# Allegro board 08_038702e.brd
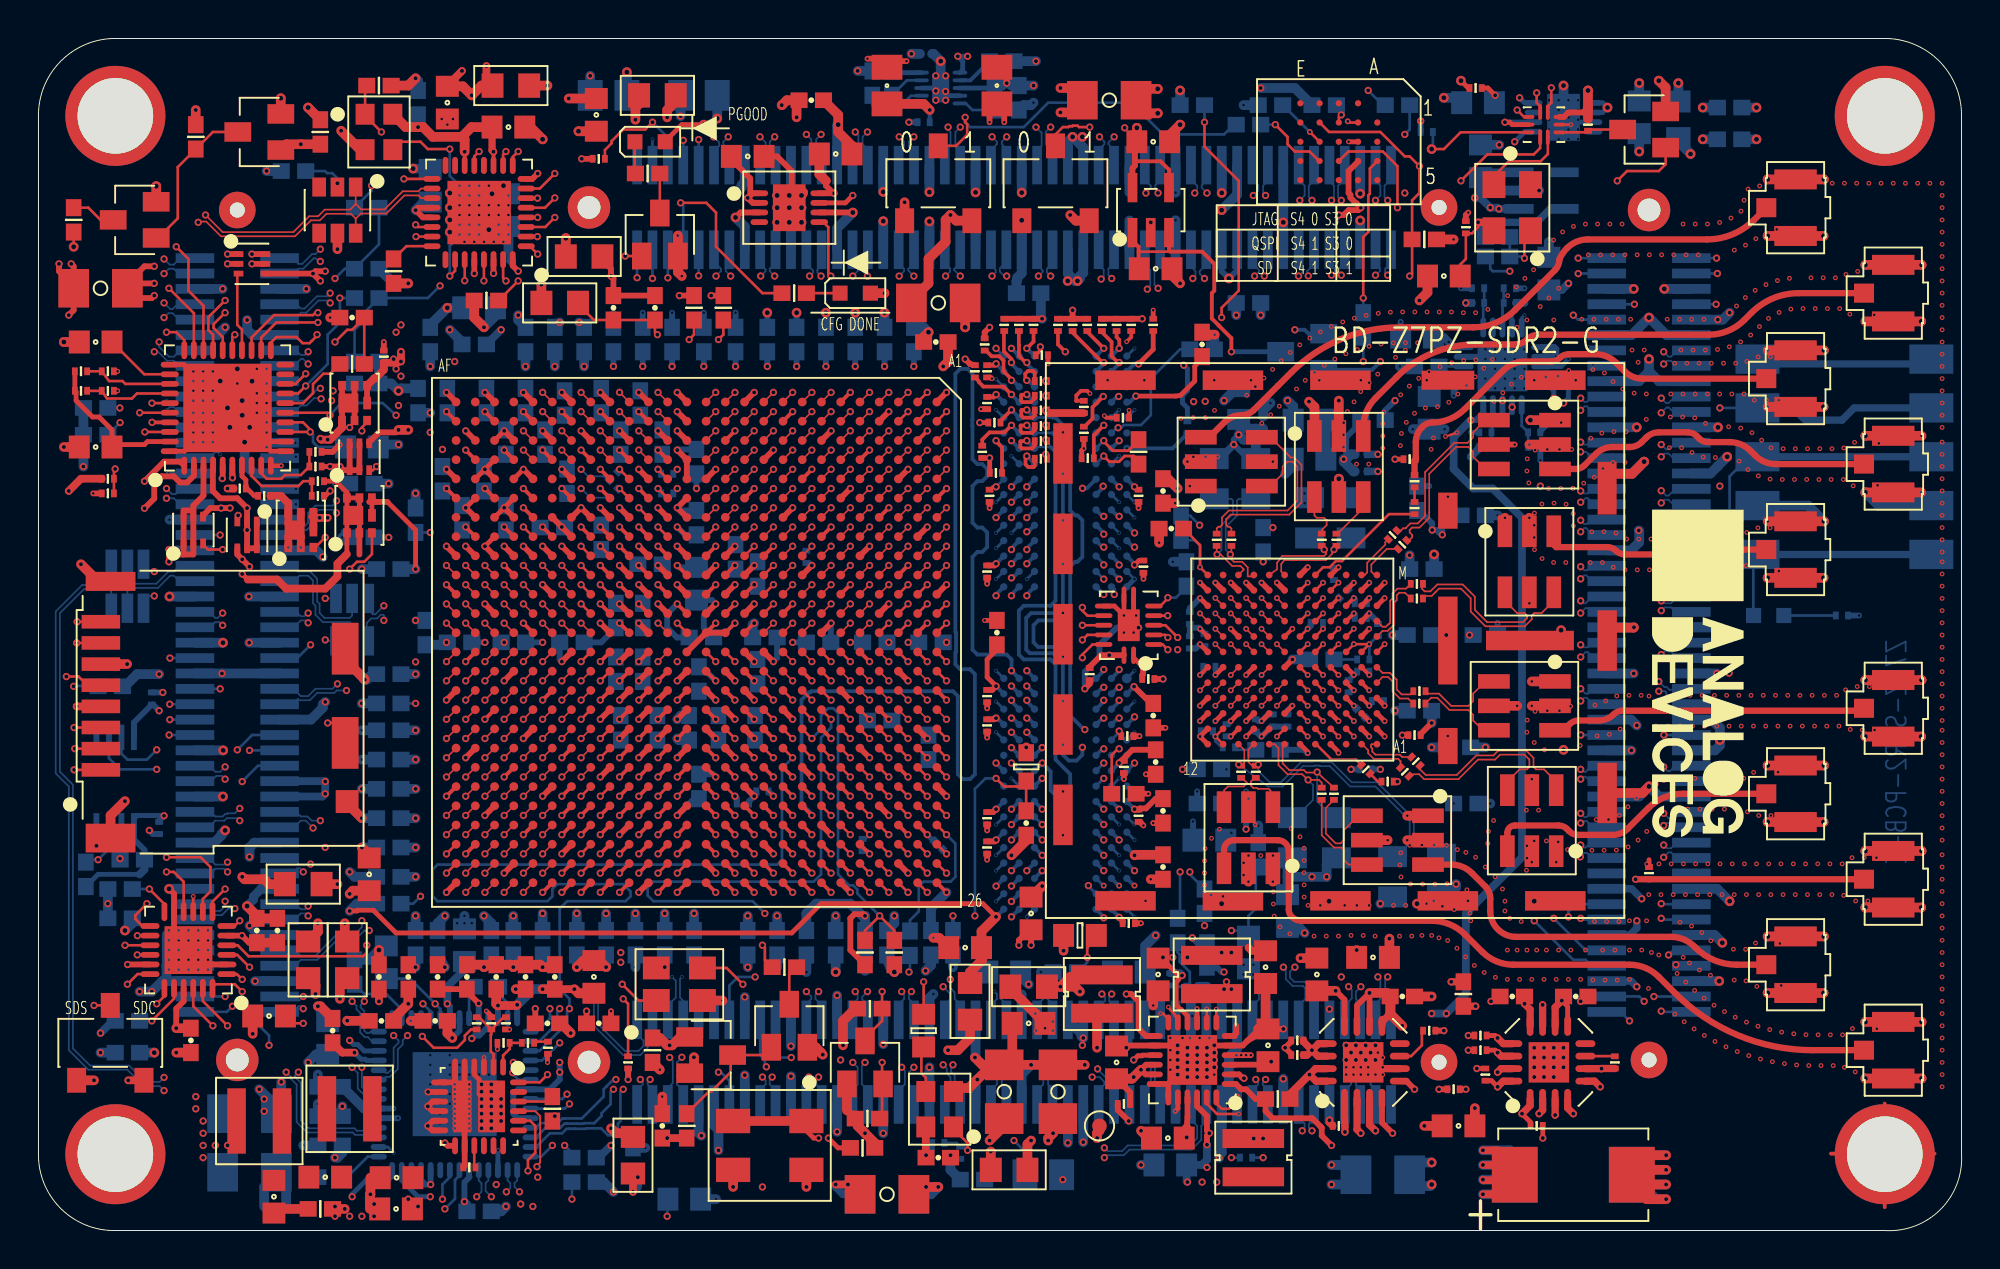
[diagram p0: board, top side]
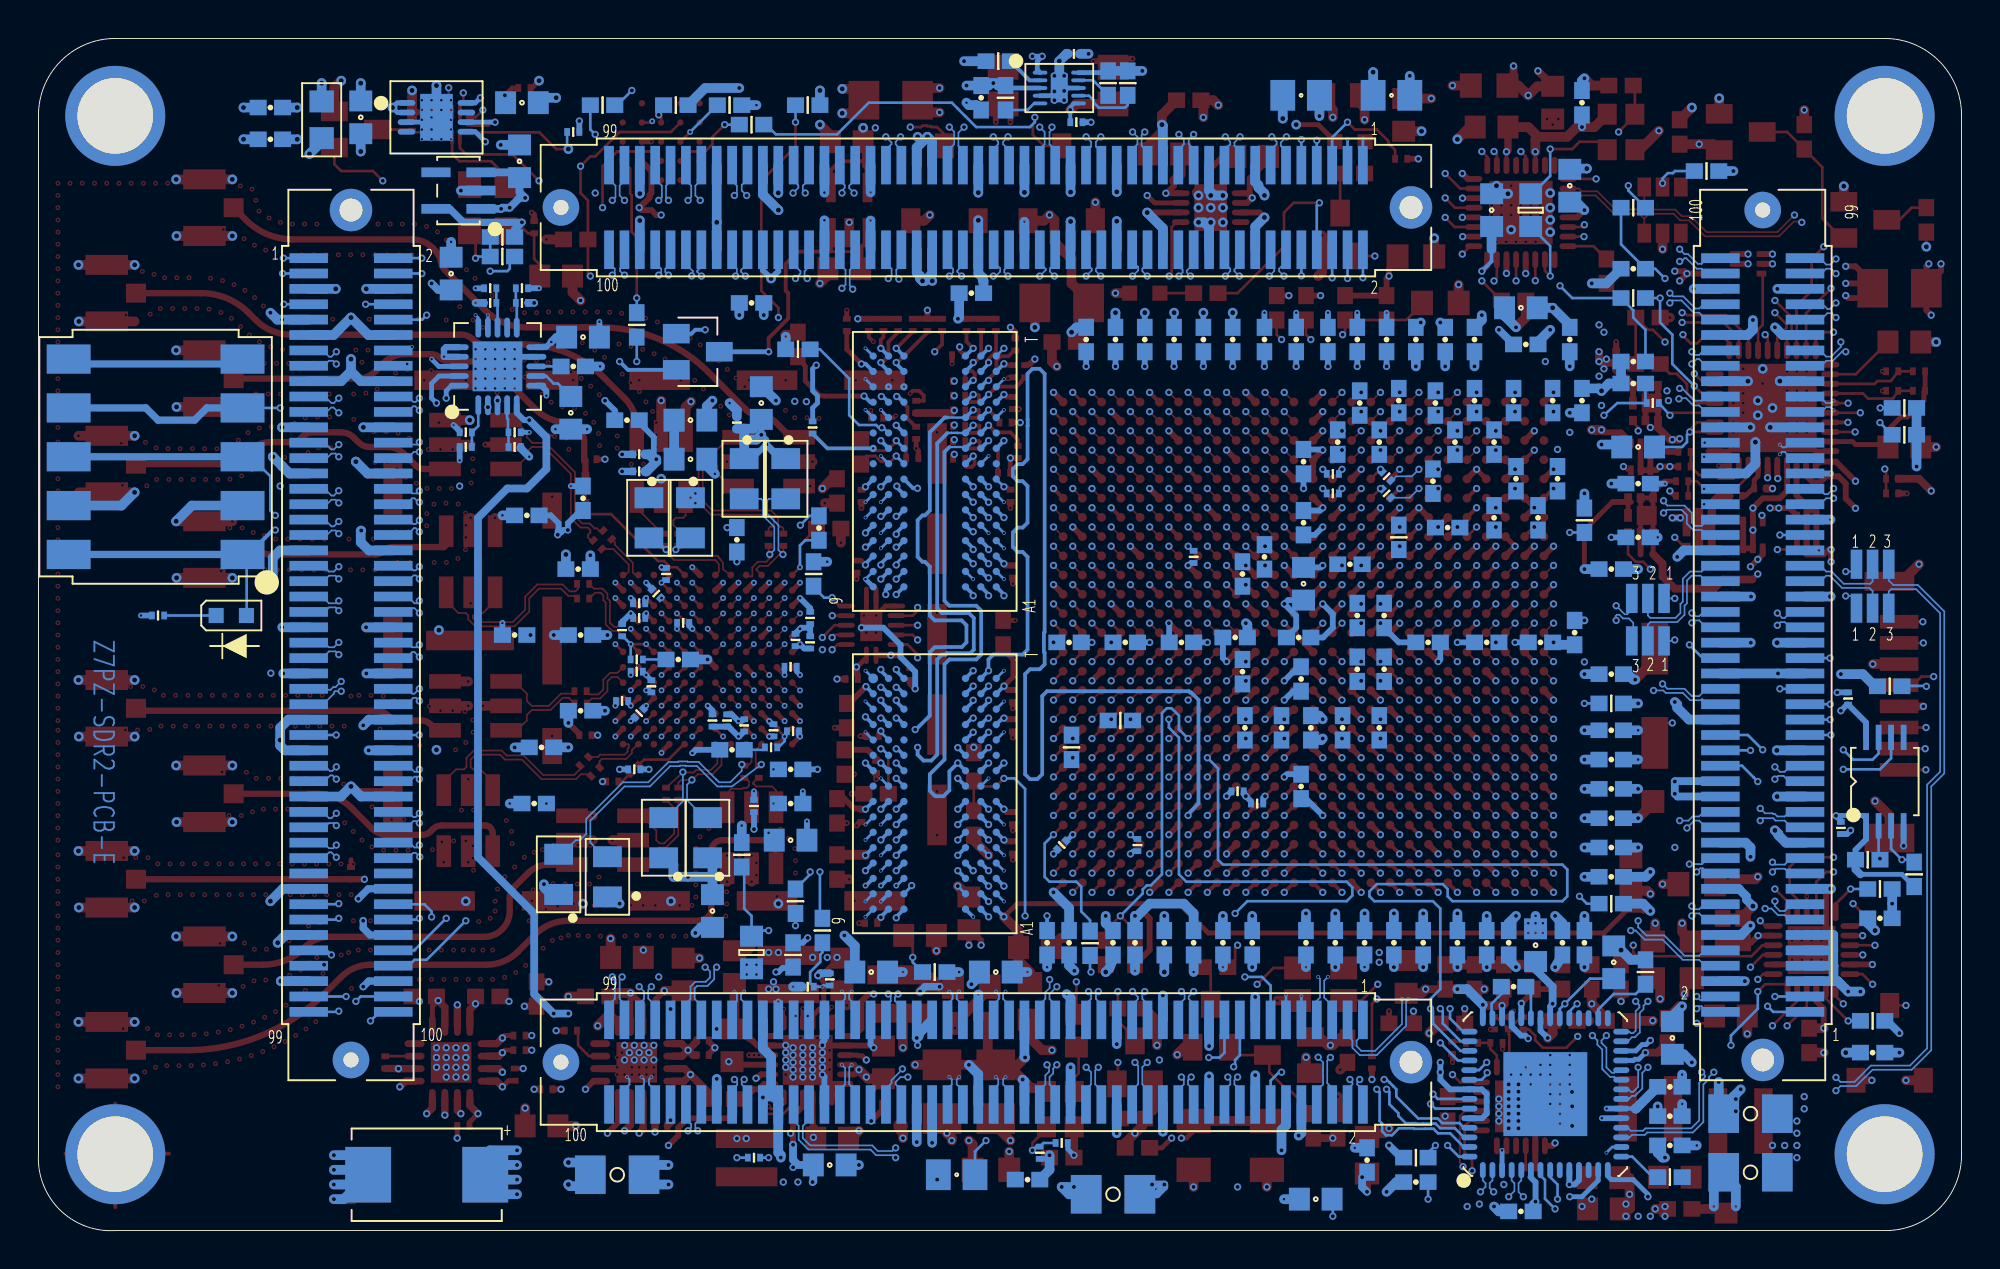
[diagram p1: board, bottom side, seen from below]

Outline 99.99 x 61.99 mm; copper layers: TOP, L2_GND, L3_SIG, L4_SIG, L5_GND, L6_SIG, L7_SIG, L8_GND, L9_POWER, L10_POWER, L11_POWER, L12_POWER, L13_GND, L14_SIG, L15_SIG, L16_GND, L17_SIG, L18_SIG, L19_GND, BOTTOM. Coordinates in mm from the lower left corner of the outline.
Outline path: 0,58 0,4 arc(1.15,1.15) 4,0 96,0 arc(98.9,1.09) 99.99,4 99.99,58 arc(98.83,60.83) 96,61.99 4,61.99 arc(1.17,60.82) 0,58

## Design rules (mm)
constraint set DEFAULT: min track width 0.14
net group DP1: nets UNNAMED_8_CAP_I284_N2 UNNAMED_8_CAP_I285_N2
net group DP2: nets UNNAMED_8_CAP_I220_N2 UNNAMED_8_CAP_I221_N2
net group DP3: nets UNNAMED_8_CAP_I137_N1 UNNAMED_8_CAP_I138_N1
net group DP4: nets UNNAMED_8_CAP_I263_N1 UNNAMED_8_CAP_I264_N1
net group DP5: nets UNNAMED_8_CAP_I209_N2 UNNAMED_8_CAP_I210_N2
net group DP6: nets UNNAMED_8_CAP_I272_N2 UNNAMED_8_CAP_I273_N2
net group DP7: nets UNNAMED_4_CN100PODDEVEN_I17_N4 UNNAMED_4_CN100PODDEVEN_I17_N5
net group DP8: nets UNNAMED_4_CN100PODDEVEN_I16_N4 UNNAMED_4_CN100PODDEVEN_I16_N5
net group DX_0: nets DX_0_N DX_0_P
net group ETH_MD1: nets ETH_MD1_N ETH_MD1_P
net group ETH_MD2: nets ETH_MD2_N ETH_MD2_P
net group ETH_MD3: nets ETH_MD3_N ETH_MD3_P
net group ETH_MD4: nets ETH_MD4_N ETH_MD4_P
net group IO_L23_12_JX2: nets IO_L23_12_JX2_N IO_L23_12_JX2_P
net group RX1A: nets RX1A_N RX1A_P
net group RX1B: nets RX1B_N RX1B_P
net group RX1C: nets UNNAMED_8_CAP_I135_N1 UNNAMED_8_CAP_I136_N1
net group RX1D: nets UNNAMED_8_CAP_I265_N1 UNNAMED_8_CAP_I266_N1
net group RX2A: nets RX2A_N RX2A_P
net group RX2B: nets RX2B_N RX2B_P
net group S_IN: nets S_IN_N S_IN_P
net group S_OUT: nets S_OUT_N S_OUT_P
net group TX1A: nets TX1A_N TX1A_P
net group TX1B: nets TX1B_N TX1B_P
net group TX2A: nets TX2A_N TX2A_P
net group TX2B: nets TX2B_N TX2B_P
net group USB_OTG: nets USB_OTG_N USB_OTG_P
net group AD9361_RX: nets IO_L01_35_RX_D0_P IO_L02_35_RX_D1_P IO_L03_35_RX_D2_P IO_L04_35_RX_D3_P IO_L05_35_RX_D4_P IO_L06_35_RX_D5_P IO_L07_35_RX_FRAME_P IO_L12_MRCC_35_DATA_CLK_P
net group AD9361_TX: nets IO_L08_35_FB_CLK_P IO_L09_35_TX_FRAME_P IO_L13_35_TX_D0_P IO_L14_35_TX_D1_P IO_L15_35_TX_D2_P IO_L16_35_TX_D3_P IO_L17_35_TX_D4_P IO_L18_35_TX_D5_P
net group CARRIER_RESET: nets CARRIER_RESET SDIO_CMDB1 VCC-3P3V-IO
net group DDR3_CK: nets DDR3_CK_N
net group DDR3_CLK2DQS: nets DDR3_DQS0_P DDR3_DQS1_P DDR3_DQS2_P DDR3_DQS3_P
net group DDR3_DQS0: nets DDR3_DQS0_N
net group DDR3_DQS1: nets DDR3_DQS1_N
net group DDR3_DQS2: nets DDR3_DQS2_N
net group DDR3_DQS3: nets DDR3_DQS3_N
net group DDR3_LANE0: nets DDR3_DM0 DDR3_DQ0 DDR3_DQ1 DDR3_DQ2 DDR3_DQ3 DDR3_DQ4 DDR3_DQ5 DDR3_DQ6 DDR3_DQ7
net group DDR3_LANE1: nets DDR3_DM1 DDR3_DQ8 DDR3_DQ9 DDR3_DQ10 DDR3_DQ11 DDR3_DQ12 DDR3_DQ13 DDR3_DQ14 DDR3_DQ15
net group DDR3_LANE2: nets DDR3_DM2 DDR3_DQ16 DDR3_DQ17 DDR3_DQ18 DDR3_DQ19 DDR3_DQ20 DDR3_DQ21 DDR3_DQ22 DDR3_DQ23
net group DDR3_LANE3: nets DDR3_DM3 DDR3_DQ24 DDR3_DQ25 DDR3_DQ26 DDR3_DQ27 DDR3_DQ28 DDR3_DQ29 DDR3_DQ30 DDR3_DQ31
net group IO_L01_12_JX3: nets IO_L01_12_JX3_N
net group IO_L01_13_JX2: nets IO_L01_13_JX2_N
net group IO_L01_33_RX_D0: nets IO_L01_35_RX_D0_N
net group IO_L01_34_JX4: nets IO_L01_34_JX4_N
net group IO_L01_35_JX1: nets IO_L01_33_JX1_N
net group IO_L02_12_JX3: nets IO_L02_12_JX3_N
net group IO_L02_13_JX2: nets IO_L02_13_JX2_N
net group IO_L02_33_RX_D1: nets IO_L02_35_RX_D1_N
net group IO_L02_34_JX4: nets IO_L02_34_JX4_N
net group IO_L02_35_JX1: nets IO_L02_33_JX1_N
net group IO_L03_12_JX3: nets IO_L03_12_JX3_N
net group IO_L03_13_JX2: nets IO_L03_13_JX2_N
net group IO_L03_33_RX_D2: nets IO_L03_35_RX_D2_N
net group IO_L03_34_JX4: nets IO_L03_34_JX4_N
net group IO_L03_35_JX1: nets IO_L03_33_JX1_N
net group IO_L04_12_JX3: nets IO_L04_12_JX3_N
net group IO_L04_13_JX2: nets IO_L04_13_JX2_N
net group IO_L04_33_RX_D3: nets IO_L04_35_RX_D3_N
net group IO_L04_34_JX4: nets IO_L04_34_JX4_N
net group IO_L04_35_JX1: nets IO_L04_33_JX1_N
net group IO_L05_12_JX3: nets IO_L05_12_JX3_N
net group IO_L05_33_JX1: nets IO_L05_33_JX1_N
net group IO_L05_33_RX_D4: nets IO_L05_35_RX_D4_N
net group IO_L05_34_JX4: nets IO_L05_34_JX4_N
net group IO_L06_12_JX3: nets IO_L06_12_JX3_N
net group IO_L06_13_JX2: nets IO_L06_13_JX2_N
net group IO_L06_33_JX1: nets IO_L06_33_JX1_N
net group IO_L06_33_RX_D5: nets IO_L06_35_RX_D5_N
net group IO_L06_34_JX4: nets IO_L06_34_JX4_N
net group IO_L07_12_JX3: nets IO_L07_12_JX3_N
net group IO_L07_13_JX2: nets IO_L07_13_JX2_N
net group IO_L07_33_RX_FRAME: nets IO_L07_35_RX_FRAME_N
net group IO_L07_34_JX4: nets IO_L07_34_JX4_N
net group IO_L07_35_JX1: nets IO_L07_33_JX1_N
net group IO_L08_12_JX3: nets IO_L08_12_JX3_N
net group IO_L08_13_JX2: nets IO_L08_13_JX2_N
net group IO_L08_33_FB_CLK: nets IO_L08_35_FB_CLK_N
net group IO_L08_34_JX4: nets IO_L08_34_JX4_N
net group IO_L08_35_JX1: nets IO_L08_33_JX1_N
net group IO_L09_12_JX3: nets IO_L09_12_JX3_N
net group IO_L09_13_JX2: nets IO_L09_13_JX2_N
net group IO_L09_33_TX_FRAME: nets IO_L09_35_TX_FRAME_N
net group IO_L09_34_JX4: nets IO_L09_34_JX4_N
net group IO_L09_35_JX1: nets IO_L09_33_JX1_N
net group IO_L10_12_JX3: nets IO_L10_12_JX3_N
net group IO_L10_13_JX2: nets IO_L10_13_JX2_N
net group IO_L10_34_JX4: nets IO_L10_34_JX4_N
net group IO_L10_35_JX1: nets IO_L10_33_JX1_N
net group IO_L11_SRCC_12_JX3: nets IO_L11_SRCC_12_JX3_N
net group IO_L11_SRCC_13_JX2: nets IO_L11_SRCC_13_JX2_N
net group IO_L11_SRCC_33_JX1: nets IO_L11_SRCC_33_JX1_N
net group IO_L11_SRCC_34_JX4: nets IO_L11_SRCC_34_JX4_N
net group IO_L12_MRCC_12_JX3: nets IO_L12_MRCC_12_JX3_N
net group IO_L12_MRCC_13_JX2: nets IO_L12_MRCC_13_JX2_N
net group IO_L12_MRCC_33_DATA_CLK: nets IO_L12_MRCC_35_DATA_CLK_N
net group IO_L12_MRCC_34_JX4: nets IO_L12_MRCC_34_JX4_N
net group IO_L12_MRCC_35_JX1: nets IO_L12_MRCC_33_JX1_N
net group IO_L13_33_TX_D0: nets IO_L13_35_TX_D0_N
net group IO_L13_MRCC_12_JX3: nets IO_L13_MRCC_12_JX3_N
net group IO_L13_MRCC_13_JX2: nets IO_L13_MRCC_13_JX2_N
net group IO_L13_MRCC_34_JX4: nets IO_L13_MRCC_34_JX4_N
net group IO_L13_MRCC_35_JX1: nets IO_L13_MRCC_33_JX1_N
net group IO_L14_33_TX_D1: nets IO_L14_35_TX_D1_N
net group IO_L14_SRCC_12_JX3: nets IO_L14_SRCC_12_JX3_N
net group IO_L14_SRCC_13_JX2: nets IO_L14_SRCC_13_JX2_N
net group IO_L14_SRCC_33_JX1: nets IO_L14_SRCC_33_JX1_N
net group IO_L14_SRCC_34_JX4: nets IO_L14_SRCC_34_JX4_N
net group IO_L15_12_JX3: nets IO_L15_12_JX3_N
net group IO_L15_13_JX2: nets IO_L15_13_JX2_N
net group IO_L15_33_JX1: nets IO_L15_33_JX1_N
net group IO_L15_33_TX_D2: nets IO_L15_35_TX_D2_N
net group IO_L15_34_JX4: nets IO_L15_34_JX4_N
net group IO_L16_12_JX3: nets IO_L16_12_JX3_N
net group IO_L16_13_JX2: nets IO_L16_13_JX2_N
net group IO_L16_33_TX_D3: nets IO_L16_35_TX_D3_N
net group IO_L16_34_JX4: nets IO_L16_34_JX4_N
net group IO_L16_35_JX1: nets IO_L16_33_JX1_N
net group IO_L17_12_JX2: nets IO_L17_12_JX2_N
net group IO_L17_13_JX2: nets IO_L17_13_JX2_N
net group IO_L17_33_TX_D4: nets IO_L17_35_TX_D4_N
net group IO_L17_34_JX4: nets IO_L17_34_JX4_N
net group IO_L17_35_JX1: nets IO_L17_33_JX1_N
net group IO_L18_12_JX2: nets IO_L18_12_JX2_N
net group IO_L18_13_JX2: nets IO_L18_13_JX2_N
net group IO_L18_33_TX_D5: nets IO_L18_35_TX_D5_N
net group IO_L18_34_JX4: nets IO_L18_34_JX4_N
net group IO_L18_35_JX1: nets IO_L18_33_JX1_N
net group IO_L19_12_JX2: nets IO_L19_12_JX2_N
net group IO_L19_13_JX2: nets IO_L19_13_JX2_N
net group IO_L19_33_JX1: nets IO_L19_33_JX1_N
net group IO_L19_34_JX4: nets IO_L19_34_JX4_N
net group IO_L20_12_JX2: nets IO_L20_12_JX2_N
net group IO_L20_13_JX2: nets IO_L20_13_JX2_N
net group IO_L20_33_JX1: nets IO_L20_33_JX1_N
net group IO_L20_34_JX4: nets IO_L20_34_JX4_N
net group IO_L21_12_JX2: nets IO_L21_12_JX2_N
net group IO_L21_13_JX2: nets IO_L21_13_JX2_N
net group IO_L21_33_JX1: nets IO_L21_33_JX1_N
net group IO_L21_34_JX4: nets IO_L21_34_JX4_N
net group IO_L22_12_JX2: nets IO_L22_12_JX2_N
net group IO_L22_13_JX2: nets IO_L22_13_JX2_N
net group IO_L22_33_JX1: nets IO_L22_33_JX1_N
net group IO_L22_34_JX4: nets IO_L22_34_JX4_N
net group IO_L23_13_JX2: nets IO_L23_13_JX2_N
net group IO_L23_33_JX1: nets IO_L23_33_JX1_N
net group IO_L24_12_JX4: nets IO_L24_12_JX4_N
net group IO_L24_13_JX2: nets IO_L24_13_JX2_N
net group IO_L24_33_JX1: nets IO_L24_33_JX1_N
net group JX_PAIRS: nets IO_00_33_JX1 IO_25_13_JX2 IO_25_33_JX1 IO_L01_12_JX3_P IO_L01_13_JX2_P IO_L01_33_JX1_P IO_L01_34_JX4_P IO_L02_12_JX3_P IO_L02_13_JX2_P IO_L02_33_JX1_P IO_L02_34_JX4_P IO_L03_12_JX3_P IO_L03_13_JX2_P IO_L03_33_JX1_P IO_L03_34_JX4_P IO_L04_12_JX3_P IO_L04_13_JX2_P IO_L04_33_JX1_P IO_L04_34_JX4_P IO_L05_12_JX3_P IO_L05_33_JX1_P IO_L05_34_JX4_P IO_L06_12_JX3_P IO_L06_13_JX2_P IO_L06_33_JX1_P IO_L06_34_JX4_P IO_L07_12_JX3_P IO_L07_13_JX2_P IO_L07_33_JX1_P IO_L07_34_JX4_P IO_L08_12_JX3_P IO_L08_13_JX2_P IO_L08_33_JX1_P IO_L08_34_JX4_P IO_L09_12_JX3_P IO_L09_13_JX2_P IO_L09_33_JX1_P IO_L09_34_JX4_P IO_L10_12_JX3_P IO_L10_13_JX2_P IO_L10_33_JX1_P IO_L10_34_JX4_P IO_L11_SRCC_12_JX3_P IO_L11_SRCC_13_JX2_P IO_L11_SRCC_33_JX1_P IO_L11_SRCC_34_JX4_P IO_L12_MRCC_12_JX3_P IO_L12_MRCC_13_JX2_P IO_L12_MRCC_33_JX1_P IO_L12_MRCC_34_JX4_P IO_L13_MRCC_12_JX3_P IO_L13_MRCC_13_JX2_P IO_L13_MRCC_33_JX1_P IO_L13_MRCC_34_JX4_P IO_L14_SRCC_12_JX3_P IO_L14_SRCC_13_JX2_P IO_L14_SRCC_33_JX1_P IO_L14_SRCC_34_JX4_P IO_L15_12_JX3_P IO_L15_13_JX2_P IO_L15_33_JX1_P IO_L15_34_JX4_P IO_L16_12_JX3_P IO_L16_13_JX2_P IO_L16_33_JX1_P IO_L16_34_JX4_P IO_L17_12_JX2_P IO_L17_13_JX2_P IO_L17_33_JX1_P IO_L17_34_JX4_P IO_L18_12_JX2_P IO_L18_13_JX2_P IO_L18_33_JX1_P IO_L18_34_JX4_P IO_L19_12_JX2_P IO_L19_13_JX2_P IO_L19_33_JX1_P IO_L19_34_JX4_P IO_L20_12_JX2_P IO_L20_13_JX2_P IO_L20_33_JX1_P IO_L20_34_JX4_P IO_L21_12_JX2_P IO_L21_13_JX2_P IO_L21_33_JX1_P IO_L21_34_JX4_P IO_L22_12_JX2_P IO_L22_13_JX2_P IO_L22_33_JX1_P IO_L22_34_JX4_P IO_L23_13_JX2_P IO_L23_33_JX1_P IO_L24_12_JX4_P IO_L24_13_JX2_P IO_L24_33_JX1_P
net group MGTREFCLK0_112_JX1: nets MGTREFCLK0_112_JX1_N
net group MGTREFCLK1_112_JX3: nets MGTREFCLK1_112_JX3_N
net group MGTX: nets MGTREFCLK0_112_JX1_P MGTREFCLK1_112_JX3_P MGTXRX0_112_JX1_P MGTXRX1_112_JX1_P MGTXRX2_112_JX1_P MGTXRX3_112_JX1_P MGTXTX0_112_JX3_P MGTXTX1_112_JX3_P MGTXTX2_112_JX3_P MGTXTX3_112_JX3_P
net group MGTXRX0_112_JX1: nets MGTXRX0_112_JX1_N
net group MGTXRX1_112_JX1: nets MGTXRX1_112_JX1_N
net group MGTXRX2_112_JX1: nets MGTXRX2_112_JX1_N
net group MGTXRX3_112_JX1: nets MGTXRX3_112_JX1_N
net group MGTXTX0_112_JX3: nets MGTXTX0_112_JX3_N
net group MGTXTX1_112_JX3: nets MGTXTX1_112_JX3_N
net group MGTXTX2_112_JX3: nets MGTXTX2_112_JX3_N
net group MGTXTX3_112_JX3: nets MGTXTX3_112_JX3_N
net group PS_MIO_A: nets PS_MIO07_500_USB_RESET_B PS_MIO09_500_USB_CLK_PD PS_MIO28_501_USB0_D4 PS_MIO29_501_USB0_DIR PS_MIO30_501_USB0_STP PS_MIO31_501_USB0_NXT PS_MIO32_501_USB0_D0 PS_MIO33_501_USB0_D1 PS_MIO34_501_USB0_D2 PS_MIO35_501_USB0_D3 PS_MIO36_501_USB0_CLK PS_MIO37_501_USB0_D5 PS_MIO38_501_USB0_D6 PS_MIO39_501_USB0_D7
net group PS_MIO_C: nets PS_MIO01_500_QSPI0_SS_B PS_MIO02_500_QSPI0_IO0 PS_MIO03_500_QSPI0_IO1 PS_MIO04_500_QSPI0_IO2 PS_MIO05_500_QSPI0_IO3 PS_MIO06_500_QSPI0_SCLK
net group PS_MIO_E: nets PS_MIO08_500_ETH0_RESETN PS_MIO16_501_ETH0_TX_CLK PS_MIO17_501_ETH0_TX_D0 PS_MIO18_501_ETH0_TX_D1 PS_MIO19_501_ETH0_TX_D2 PS_MIO20_501_ETH0_TX_D3 PS_MIO21_501_ETH0_TX_CTL PS_MIO22_501_ETH0_RX_CLK PS_MIO23_501_ETH0_RX_D0 PS_MIO24_501_ETH0_RX_D1 PS_MIO25_501_ETH0_RX_D2 PS_MIO26_501_ETH0_RX_D3 PS_MIO27_501_ETH0_RX_CTL PS_MIO52_501_ETH0_MDC PS_MIO53_501_ETH0_MDIO

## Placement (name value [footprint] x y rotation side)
C1  0.01uF  [C0201]  69.65 27.54 0 bottom
C2  1uF  [C0402]  75.24 30.97 0 bottom
C3  1uF  [C0402]  69.39 42.15 0 bottom
C4  0.01uF  [C0201]  68.12 28.3 90 bottom
C5  4.7uF  [C0603]  73.08 49.64 180 top
C6  0.001uF  [C0201]  71.55 37.57 270 top
C7  0.001uF  [C0201]  69.01 23.98 135 top
C8  18pF  [C0201]  70.41 36.18 225 top
C9  18pF  [C0201]  70.92 35.67 225 top
C10  18pF  [C0201]  71.62 24.4 135 top
C11  18pF  [C0201]  71.05 23.86 135 top
C12  1uF  [C0402]  66.73 29.7 180 bottom
C13  0.001uF  [C0201]  69.65 31.22 90 bottom
C14  0.001uF  [C0201]  68.76 39.48 180 bottom
C15  4.7uF  [C0402]  37.9 46.34 90 bottom
C16  0.001uF  [C0201]  68.76 40.37 180 bottom
C17  4.7uF  [C0402]  34.6 46.34 90 bottom
C18  0.47uF  [C0402]  31.42 46.34 90 bottom
C19  0.001uF  [C0201]  62.79 22.08 270 bottom
C20  0.001uF  [C0201]  63.68 42.02 270 bottom
C21  10uF  [C0603]  66.09 40.11 180 bottom
C22  10uF  [C0603]  66.09 42.15 180 bottom
C23  10uF  [C0603]  64.95 16.62 270 bottom
C24  10uF  [C0603]  62.41 43.03 90 bottom
C25  18pF  [C0201]  66.73 35.92 90 top
C26  18pF  [C0201]  67.49 35.92 90 top
C27  0.47uF  [C0402]  40.95 46.34 90 bottom
C28  0.1uF  [C0402]  26.85 46.34 90 bottom
C29  18pF  [C0201]  61.27 35.92 90 top
C30  18pF  [C0201]  62.03 35.92 90 top
C31  0.1uF  [C0402]  43.99 46.34 90 bottom
C32  18pF  [C0201]  67.36 22.71 270 top
C33  18pF  [C0201]  66.73 22.71 270 top
C34  18pF  [C0201]  63.3 23.86 270 top
C35  18pF  [C0201]  62.54 23.86 270 top
C36  1uF  [C0603]  41.45 55.99 0 top
C37  0.1uF  [C0402]  46.41 30.59 0 bottom
C38  10uF  [C0603]  36.88 55.86 0 top
C39  0.1uF  [C0402]  46.79 3.79 0 top
C40  0.1uF  [C0402]  62.92 48.24 0 bottom
C41  0.1uF  [C0402]  7.93 9.89 270 top
C42  0.1uF  [C0402]  4.24 16.24 0 bottom
C43  0.01uF  [C0201]  46.15 61.2 180 bottom
C44  680uF  [CPLSML287W169H118]  79.81 2.9 0 top
C45  0.1uF  [C0201]  32.69 39.35 180 bottom
C46  0.1uF  [C0201]  29.9 38.34 45 bottom
C47  0.1uF  [C0201]  32.69 38.34 180 bottom
C48  0.1uF  [C0201]  29.9 39.22 45 bottom
C49  4.7uF  [C0402]  17.71 13.19 90 top
C50  4.7uF  [C0402]  26.47 10.78 0 top
C51  18pF  [C0201]  71.67 33.63 180 top
C52  18pF  [C0201]  71.67 32.87 180 top
C53  18pF  [C0201]  71.81 28.05 180 top
C54  0.1uF  [C0402]  11.36 15.6 90 top
C55  0.1uF  [C0402]  12.42 15.6 90 top
C56  18pF  [C0201]  71.8 27.41 180 top
C57  0.1uF  [C0402]  4.62 9.25 0 bottom
C58  1uF  [C0603]  28.88 13.19 90 top
C59  27PF  [C0603]  11.99 11.16 180 top
C60  27PF  [C0603]  18.09 13.95 90 bottom
C61  10uF  [C0603]  58.73 4.81 180 top
C62  10uF  [C0603]  63.93 9.63 90 top
C63  4.7uF  [C0402]  26.85 13.19 90 top
C64  4.7uF  [C0402]  26.34 41 90 bottom
C65  10uF  [C0603]  56.06 8.74 90 top
C66  0.1uF  [C0201]  56.44 6.59 180 top
C67  22uF  [C0603]  58.22 13.32 270 top
C68  22uF  [C0603]  63.81 13.7 270 top
C69  22uF  [C0603]  58.85 3.41 180 bottom
C70  4.7uF  [C0402]  29.9 46.34 90 bottom
C71  4.7uF  [C0402]  45.52 46.34 90 bottom
C72  0.47uF  [C0402]  42.47 46.34 90 bottom
C73  0.1uF  [C0402]  23.8 13.19 90 top
C74  4.7uF  [C0402]  15.17 4.43 180 bottom
C75  0.1uF  [C0402]  22.91 1 0 bottom
C76  0.01uF  [C0201]  37.64 22.84 180 bottom
C77  0.01uF  [C0201]  36.63 22.21 0 bottom
C78  1uF  [C0603]  17.2 18.52 90 top
C79  10uF  [C0805H60]  49.84 59.54 270 top
C80  0.015uF  [C0402]  50.98 58.91 270 bottom
C81  0.22UF  [C0805]  44.12 59.54 90 top
C82  10uF  [C0805H60]  34.34 59.04 0 bottom
C83  10uF  [C0805H60]  29.64 59.04 0 bottom
C84  0.01uF  [C0201]  46.03 57.64 180 bottom
C85  680uF  [CPLSML287W169H118]  79.81 2.9 0 bottom
C86  4.7uF  [C0402]  58.47 18.9 270 top
C87  4.7uF  [C0402]  58.09 24.37 270 top
C88  0.47uF  [C0402]  57.96 26.78 270 top
C89  0.47uF  [C0402]  58.47 21.83 270 top
C90  0.47uF  [C0402]  32.95 46.34 90 bottom
C91  0.1uF  [C0201]  56.69 15.98 0 top
C92  0.1uF  [C0201]  49.33 19.92 270 top
C93  0.1uF  [C0402]  36.25 46.34 90 bottom
C94  0.1uF  [C0201]  56.44 24.11 270 top
C95  0.1uF  [C0201]  57.2 21.57 270 top
C96  0.1uF  [C0201]  49.33 27.79 270 top
C97  0.1uF  [C0201]  49.33 26.27 270 top
C98  0.1uF  [C0402]  39.42 46.34 90 bottom
C99  4.7uF  [C0402]  25.33 46.34 90 bottom
C100  100uF  [C1206H71]  55.68 58.78 0 top
C101  4.7uF  [C0402]  51.49 48.75 180 bottom
C102  0.01uF  [C0201]  49.46 38.21 270 top
C103  0.01uF  [C0201]  49.33 21.44 270 top
C104  0.001uF  [C0201]  60.76 25.97 0 bottom
C105  1uF  [C0402]  63.93 25 0 bottom
C106  4.7uF  [C0402]  60.5 46.08 90 top
C107  0.47uF  [C0402]  58.47 38.46 270 top
C108  0.47uF  [C0402]  49.84 31.1 90 top
C109  0.1uF  [C0201]  49.33 34.27 270 top
C110  4.7uF  [C0402]  44.12 14.97 270 bottom
C111  4.7uF  [C0402]  18.21 24.49 180 bottom
C112  0.1uF  [C0201]  49.33 43.03 270 top
C113  0.1uF  [C0201]  74.22 52.18 90 top
C114  0.47uF  [C0402]  28.37 46.34 90 bottom
C115  0.1uF  [C0201]  49.33 44.69 270 top
C116  0.1uF  [C0201]  57.96 47.1 90 top
C117  0.1uF  [C0201]  57.2 38.21 270 top
C118  0.1uF  [C0201]  57.46 34.53 270 top
C119  0.1uF  [C0402]  36.25 35.03 90 bottom
C120  4.7uF  [C0402]  40.18 58.78 0 top
C121  4.7uF  [C0402]  31.04 14.97 270 bottom
C122  0.01uF  [C0201]  56.39 42.27 180 top
C123  0.01uF  [C0201]  56.62 25.71 180 top
C124  10uF  [C0603]  71.68 46.46 180 bottom
C125  0.47uF  [C0402]  48.57 2.65 180 bottom
C126  0.1uF  [C0402]  27.99 14.97 270 bottom
C127  0.1uF  [C0402]  36.88 14.97 270 bottom
C128  0.1uF  [C0402]  29.52 14.97 270 bottom
C129  0.1uF  [C0402]  32.56 14.97 270 bottom
C130  0.1uF  [C0402]  34.34 23.1 270 bottom
C131  0.1uF  [C0402]  41.45 14.97 270 bottom
C132  0.1uF  [C0402]  18.21 18.4 180 bottom
C133  4.7uF  [C0402]  72.19 44.94 180 bottom
C134  10uF  [C0603]  78.54 49.77 90 bottom
C135  0.1uF  [C0402]  18.21 22.97 180 bottom
C136  0.1uF  [C0402]  38.41 14.97 270 bottom
C137  0.1uF  [C0402]  34.09 14.97 270 bottom
C138  100uF  [C1206H71]  50.22 7.22 90 top
C139  100uF  [C1206H71]  53.01 7.22 90 top
C140  4.7uF  [C0402]  37.39 29.06 90 bottom
C141  4.7uF  [C0402]  37.39 34.14 90 bottom
C142  4.7uF  [C0402]  30.02 31.99 90 bottom
C143  0.47uF  [C0402]  31.42 29.19 270 bottom
C144  4.7uF  [C0402]  18.21 28.94 180 bottom
C145  0.47uF  [C0402]  46.66 46.21 180 top
C146  0.47uF  [C0402]  18.21 19.92 180 bottom
C147  0.1uF  [C0402]  47.55 14.97 270 bottom
C148  0.1uF  [C0402]  34.34 28.68 270 bottom
C149  0.1uF  [C0402]  34.47 30.84 0 bottom
C150  0.1uF  [C0402]  27.74 30.59 180 bottom
C151  0.1uF  [C0402]  31.42 31.99 270 bottom
C152  0.1uF  [C0402]  37.77 30.84 0 bottom
C153  0.47uF  [C0402]  23.55 14.97 270 bottom
C154  0.1uF  [C0402]  34.22 39.99 90 bottom
C155  0.1uF  [C0402]  30.02 29.19 90 bottom
C156  0.1uF  [C0402]  24.69 30.59 180 bottom
C157  0.1uF  [C0402]  26.21 14.97 270 bottom
C158  10uF  [C0603]  72.32 42.53 270 bottom
C159  4.7uF  [C0402]  33.83 26.14 90 bottom
C160  0.1uF  [C0402]  18.21 21.44 180 bottom
C161  4.7uF  [C0402]  35.36 26.14 270 bottom
C162  0.47uF  [C0402]  30.28 26.14 270 bottom
C163  0.47uF  [C0402]  32.18 26.14 270 bottom
C164  0.1uF  [C0402]  37.26 26.14 270 bottom
C165  18PF  [C0402]  58.9 36.51 180 top
C166  0.1uF  [C0402]  22.66 46.08 180 bottom
C167  4.7uF  [C0402]  18.21 26.02 180 bottom
C168  0.1uF  [C0402]  19.74 58.66 90 bottom
C169  4.7uF  [C0402]  20.75 14.97 270 bottom
C170  0.47uF  [C0402]  20.12 31.1 270 bottom
C171  0.47uF  [C0402]  18.21 34.4 180 bottom
C172  100uF  [C1206H71]  46.79 48.24 0 top
C173  100uF  [C1206H71]  69.9 2.9 0 bottom
C174  4.7uF  [C0402]  39.93 14.97 270 bottom
C175  4.7uF  [C0402]  21.9 30.59 180 bottom
C176  4.7uF  [C0402]  46.41 14.97 270 bottom
C177  4.7uF  [C0402]  42.98 14.97 270 bottom
C178  0.47uF  [C0402]  51.36 21.19 270 top
C179  0.47uF  [C0402]  34.22 36.81 90 bottom
C180  100uF  [C1206H71]  3.23 49 180 top
C181  1uF  [C0603]  24.44 53.07 90 bottom
C182  1uF  [C0603]  22.91 47.99 180 bottom
C183  1uF  [C0603]  24.44 57.39 0 top
C184  1uF  [C0603]  20.37 54.34 90 bottom
C185  0.1uF  [C0402]  19.61 14.97 270 bottom
C186  0.1uF  [C0402]  24.69 14.97 270 bottom
C187  0.1uF  [C0402]  31.8 34.65 0 bottom
C188  0.1uF  [C0201]  74.73 59.42 180 top
C189  0.47uF  [C0402]  29.9 47.99 90 top
C190  0.1uF  [C0402]  32.06 47.99 90 top
C191  10uF  [C0603]  51.49 10.78 180 top
C192  10uF  [C0603]  48.19 14.71 180 top
C193  10uF  [C0603]  51.61 16.49 90 top
C194  10uF  [C0603]  50.22 13.44 180 bottom
C195  10uF  [C0603]  56.69 13.44 180 bottom
C196  10uF  [C0603]  21.26 58.66 270 top
C197  10uF  [C0603]  29.01 58.02 270 top
C198  10uF  [C0603]  34.22 33.64 270 bottom
C199  1uF  [C0603]  74.86 58.66 180 bottom
C200  10uF  [C0603]  83.24 57.89 270 bottom
C201  0.1uF  [C0402]  20.75 13.19 90 top
C202  10uF  [C0603]  16.82 40.75 0 bottom
C203  0.1uF  [C0402]  17.83 10.9 180 top
C204  10uF  [C0603]  2.97 46.21 180 top
C205  10uF  [C0603]  2.97 40.75 180 top
C206  0.1uF  [C0402]  15.17 5.95 180 bottom
C207  220pF  [C0402]  17.07 44.05 0 bottom
C208  0.1uF  [C0402]  15.29 10.4 90 top
C209  220pF  [C0402]  16.31 47.48 180 top
C210  10uF  [C0603]  22.15 14.84 90 bottom
C211  0.1uF  [C0402]  19.23 13.19 90 top
C212  0.1uF  [C0402]  30.91 3.66 90 bottom
C213  220pF  [C0402]  17.07 45.19 0 bottom
C214  0.1uF  [C0402]  15.17 7.47 180 bottom
C215  220pF  [C0402]  17.07 50.02 0 bottom
C216  18PF  [C0402]  59.41 36.53 270 bottom
C217  0.1uF  [C0402]  25.33 13.19 90 top
C218  4.7uF  [C0402]  22.28 13.19 90 top
C219  1uF  [C0603]  15.04 10.01 90 bottom
C220  4.7uF  [C0402]  16.82 38.84 180 bottom
C221  4.7uF  [C0402]  19.74 43.16 90 bottom
C222  0.47uF  [C0402]  16.82 36.05 180 bottom
C223  4.7uF  [C0402]  20.37 46.34 90 bottom
C224  0.1uF  [C0402]  32.44 5.44 90 top
C225  0.1uF  [C0402]  29.14 10.78 0 top
C226  0.1uF  [C0402]  20.63 10.9 180 top
C227  0.1uF  [C0402]  30.28 41 90 bottom
C228  0.47uF  [C0402]  31.29 43.03 90 bottom
C229  0.1uF  [C0402]  23.17 39.1 90 bottom
C230  0.1uF  [C0402]  25.33 43.16 90 bottom
C231  0.1uF  [C0402]  26.72 36.56 0 bottom
C232  0.1uF  [C0402]  21.01 39.1 90 bottom
C233  0.1uF  [C0402]  32.44 41 90 bottom
C234  0.1uF  [C0402]  24.31 41 90 bottom
C235  0.1uF  [C0402]  24.31 37.07 90 bottom
C236  0.1uF  [C0402]  29.26 43.16 90 bottom
C237  0.1uF  [C0402]  22.02 37.07 90 bottom
C238  0.1uF  [C0402]  21.26 43.16 90 bottom
C239  0.1uF  [C0402]  27.48 38.97 90 bottom
C240  0.1uF  [C0402]  23.29 43.16 90 bottom
C241  0.1uF  [C0402]  27.36 43.03 90 bottom
C242  0.1uF  [C0402]  23.29 12.68 180 bottom
C243  0.1uF  [C0201]  6.28 20.94 90 bottom
C244  0.1uF  [C0201]  5.89 27.67 270 bottom
C245  0.1uF  [C0201]  57.71 28.68 0 top
C246  0.1uF  [C0201]  54.66 28.94 270 top
C247  2.2uF  [C0603]  58.09 50.02 0 top
C248  2.2uF  [C0603]  57.96 56.62 0 top
C249  0.1uF  [C0402]  40.57 30.59 0 bottom
C250  0.1uF  [C0402]  43.49 30.59 0 bottom
C251  47uF  [C0805H60]  52.25 2.9 0 bottom
C252  0.039uF  [C0603]  33.58 1.63 0 bottom
C253  0.1uF  [C0201]  22.4 3.28 0 top
C254  1uF  [C0402]  28.37 2.52 0 bottom
C255  0.0022uF  [C0201]  25.45 9.76 0 top
C256  39PF  [C0201]  24.18 9.76 180 top
C257  2.2UF  [C0603]  12.24 1.76 270 top
C258  100uF  [C1206H71]  44.12 1.89 0 top
C259  100uF  [C1206H71]  44.12 1.89 0 bottom
C260  4.7uF  [C0603]  74.98 55.61 90 bottom
C301  10uF  [C0603]  18.59 1.12 180 top
C305  2.2uF  [C0603]  14.91 2.78 0 top
C308  100uF  [C1206H71]  10.97 6.08 0 bottom
C309  100uF  [C1206H71]  10.97 3.03 0 bottom
C310  0.1uF  [C0201]  77.9 5.44 0 top
C311  0.01uF  [C0201]  72.32 10.4 0 top
C312  10uF  [C0603]  69.39 14.21 0 top
C313  10uF  [C0603]  66.47 13.32 90 top
C314  0.1uF  [C0201]  65.46 9.89 180 top
C315  0.1uF  [C0201]  65.46 9.13 180 top
C318  0.1uF  [C0201]  67.62 5.44 180 top
C319  0.1uF  [C0201]  64.19 26.52 90 bottom
C320  1uF  [C0402]  70.92 12.17 0 top
C321  0.01uF  [C0201]  61.77 26.02 90 bottom
C322  0.01uF  [C0201]  68.89 29.06 180 bottom
C323  1uF  [C0402]  71.81 27.03 0 bottom
C324  1uF  [C0402]  71.68 38.08 90 bottom
C325  0.01uF  [C0201]  68.76 26.91 315 bottom
C326  0.01uF  [C0201]  68.76 32.62 0 bottom
C327  1uF  [C0402]  71.93 34.4 0 bottom
C328  1uF  [C0402]  71.81 30.97 0 bottom
C329  0.01uF  [C0201]  68.76 31.86 0 bottom
C330  0.01uF  [C0201]  60.89 29.32 0 bottom
C331  1uF  [C0402]  74.6 37.19 0 bottom
C332  1uF  [C0402]  74.22 22.21 0 bottom
C333  0.01uF  [C0201]  67.87 33.13 45 bottom
C334  0.01uF  [C0201]  69.01 23.98 0 bottom
C335  1uF  [C0402]  63.68 35.92 90 bottom
C336  1uF  [C0402]  73.84 25.13 0 bottom
C337  0.01uF  [C0201]  71.55 25.76 0 top
C340  0.01uF  [C0201]  81.97 8.74 270 top
C341  10uF  [C0402]  79.94 12.17 0 top
C342  10uF  [C0402]  76.63 12.17 180 top
C343  0.1uF  [C0201]  74.98 10.14 180 top
C344  0.1uF  [C0201]  74.98 9.38 180 top
C347  0.1uF  [C0201]  75.24 8.11 90 top
C348  0.1uF  [C0201]  59.87 31.86 90 bottom
C354  1uF  [C0402]  60.89 23.98 180 bottom
C355  0.01uF  [C0201]  60.63 30.72 270 bottom
C356  0.01uF  [C0201]  59.87 30.59 270 bottom
C357  1uF  [C0402]  60.89 22.21 180 bottom
C358  1uF  [C0402]  87.94 56.75 0 bottom
C359  0.01uF  [C0201]  63.3 26.27 90 bottom
C360  0.01uF  [C0201]  64.95 26.52 90 bottom
C361  1uF  [C0402]  87.94 58.4 0 bottom
C362  10uF  [C0603]  73.84 5.44 180 top
C363  10uF  [C0603]  60.89 20.3 180 bottom
C364  0.1uF  [C0201]  17.96 45.45 90 top
C365  10uF  [C0603]  18.62 2.75 180 top
D1  BAT54C  [SOT23]  65.71 45.7 270 bottom
D3  LG L29K-G2J1-24-Z  [LED0603-2]  31.8 56.62 0 top
D4  LG L29K-G2J1-24-Z  [LED0603-2]  42.47 48.75 0 top
DS1  LG L29K-G2J1-24-Z  [LED0603-2]  89.97 31.99 180 bottom
E1  220OHM  [L0805]  27.1 48.24 0 top
E2  100OHM  [L0805]  50.47 3.16 180 top
E3  100OHM  [L0805]  48.44 11.92 90 top
E4  100OHM  [L0805]  51.49 12.68 180 top
E7  100OHM  [L0805]  24.56 59.54 180 top
E8  100OHM  [L0805]  32.18 59.04 180 top
E9  100OHM  [L0805]  14.02 14.08 90 top
E10  75OHM  [L0402]  74.09 12.3 90 top
E11  100OHM  [L0805]  85.27 57.77 270 bottom
E12  220OHM  [L0805]  28.37 50.65 0 top
E14  100OHM  [L0805]  30.91 3.92 270 top
E15  100OHM  [L0805]  13.77 18.02 0 top
E16  100OHM  [L0805]  16.05 14.08 270 top
J3  DM3CS-SF  [CNHIROSEDM3CS-SF]  9.45 27.16 0 top
JP1  3PIN_SOLDER_JUMPER  [JPRSLD03]  4.62 32.37 180 bottom
JP2  3PIN_SOLDER_JUMPER  [JPRSLD03]  4.62 34.65 180 bottom
JP3  3PIN_SOLDER_JUMPER  [JPRSLD03]  16.31 30.66 0 bottom
JP4  3PIN_SOLDER_JUMPER  [JPRSLD03]  16.31 32.87 0 bottom
JX1  61082-101400LF  [CNFCI61082-101400]  50.73 53.21 0 bottom
JX2  61082-101400LF  [CNFCI61082-101400]  50.73 8.76 0 bottom
JX3  61082-101400LF  [CNFCI61082-101400]  10.34 30.97 90 bottom
JX4  61082-101400LF  [CNFCI61082-101400]  83.75 30.97 270 bottom
L1  330NH  [L0805-F]  61.14 39.1 270 bottom
L2  330NH  [L0805-F]  63.3 39.1 270 bottom
L3  330NH  [L0805-F]  72.95 18.52 90 bottom
L4  330NH  [L0805-F]  70.41 18.4 90 bottom
L5  1uH  [LSMSQ118H47]  55.3 12.3 90 top
L6  1uH  [LSMSQ118H47]  61.01 13.32 90 top
L7  1uH  [LSMSQ118H47]  63.17 3.79 270 top
L8  330NH  [L0805-F]  66.09 37.07 270 bottom
L9  330NH  [L0805-F]  68.25 37.07 270 bottom
L10  330NH  [L0805-F]  67.49 20.43 90 bottom
L11  330NH  [L0805-F]  65.2 20.43 90 bottom
L12  600OHMS  [L0603]  51.36 24.11 270 top
L13  330nH  [LSMSQ157H63]  11.48 5.7 180 top
L301  700nH  [LSMSQ157H63]  16.18 6.33 180 top
M1  LT15CCC2243A  [MLT15CCC2243A]  67.42 30.68 180 top
NOREF  -  []  3.99 -0.02 90 top
NOREF#2  -  []  -89.23 -241.57 0 top
NOREF#3  -  [unnamed#2]  4 3.97 0 top
NOREF#4  -  []  109.2 68.22 0 top
NOREF#5  -  []  0 4 0 top
NOREF#6  -  []  -0.07 -0.13 0 top
NOREF#7  -  []  226.11 149.71 0 top
NOREF#8  -  [unnamed#2]  4 57.97 0 top
NOREF#9  -  []  100.13 -0.13 90 top
NOREF#10  -  []  -0.07 62.07 270 top
NOREF#11  -  [unnamed#2]  96 3.97 0 top
NOREF#12  -  []  -76.66 -229 0 top
NOREF#13  -  []  -7.69 68.22 0 top
NOREF#14  -  []  4 3.97 90 top
NOREF#15  -  []  4 3.97 0 top
NOREF#16  -  []  278.21 -114.19 0 top
NOREF#17  -  []  3.99 -0.02 90 top
NOREF#18  -  []  -7.69 -6.25 0 top
NOREF#19  -  []  248.21 130.03 0 top
NOREF#20  -  [unnamed#2]  96 57.97 0 top
NOREF#21  -  []  4 3.97 90 top
NOREF#22  -  []  100.13 62.07 180 top
NOREF#23  -  []  4 3.97 90 top
NOREF#24  -  []  53.14 82.28 0 top
NOREF#25  -  []  4 3.97 0 top
NOREF#26  -  []  98.94 60.71 0 top
NOREF#27  -  []  86.29 28.94 270 top
NOREF#28  -  []  0 3.99 0 top
P1  5147733-4  [CNTE5147733-4]  93.91 40.24 90 bottom
Q1  BSS138TA  [SOT23]  34.98 9.13 270 top
Q2  BSS138TA  [SOT23]  11.48 57.13 90 top
Q3  BSS138TA  [SOT23]  39.04 10.65 0 top
Q4  BSS138TA  [SOT23]  5.01 52.56 90 top
Q5  BSS138LT1G  [SOT23]  42.98 8.74 0 top
Q6  BSS138LT1G  [SOT23]  83.49 57.26 90 top
Q7  SI1050X-T1-GE3  [SOT-563]  10.85 36.18 180 top
Q8  SI1050X-T1-GE3  [SOT-563]  8.05 36.43 0 top
Q9  FDMA430NZ  [MLP6_2X2_PAD_9X1_PAD_2X_56]  16.69 37.19 0 top
Q10  SI1050X-T1-GE3  [SOT-563]  16.69 40.24 0 top
Q11  FDMA430NZ  [MLP6_2X2_PAD_9X1_PAD_2X_56]  13.64 36.43 0 top
Q12  SI1050X-T1-GE3  [SOT-563]  11.1 50.27 270 top
Q13  FDMA430NZ  [MLP6_2X2_PAD_9X1_PAD_2X_56]  16.44 43.03 0 top
Q14  BSS138LT1G  [SOT23]  32.31 51.8 0 top
R1  10  [R0201]  71.55 38.97 270 top
R2  10  [R0201]  70.16 23.35 180 top
R3  20K  [R0402]  42.85 4.3 180 top
R4  4.99K  [R0402]  4.24 17.76 0 bottom
R5  49.9  [R0201]  72.19 57.13 180 bottom
R6  0  [R0402]  50.09 60.81 180 bottom
R7  10K  [R0402]  43.11 5.82 0 top
R8  10K  [R0402]  43.23 11.54 0 top
R9  0  [R0402]  23.29 48.37 0 top
R10  100  [R0402]  19.61 36.94 270 bottom
R11  4.99K  [R0402]  28.37 3.79 180 bottom
R12  0  [R0402]  15.17 2.78 0 bottom
R13  1K  [R0402]  31.93 9.38 270 top
R14  1K  [R0402]  14.66 57.13 90 top
R15  1K  [R0402]  33.71 5.44 90 top
R16  1K  [R0402]  8.18 56.88 270 top
R17  220  [R0402]  38.79 13.7 180 top
R18  220  [R0402]  1.83 52.56 270 top
R19  0  [R0402]  68.89 47.1 90 bottom
R20  10K  [R0201]  60 12.68 0 bottom
R21  10K  [R0402]  53.39 13.44 180 bottom
R22  10K  [R0402]  63.43 19.54 90 bottom
R23  10K  [R0201]  58.85 13.06 90 bottom
R24  16.9K  [R0603]  54.15 15.35 180 top
R25  26.1K  [R0603]  62.92 14.46 270 bottom
R26  10K  [R0402]  46.28 25.13 90 bottom
R27  10K  [R0402]  17.71 59.54 0 top
R28  240  [R0402]  66.85 58.53 0 bottom
R29  10K  [R0402]  60.76 14.33 270 bottom
R30  10K  [R0201]  2.21 44.69 0 top
R31  20K  [R0201]  42.85 20.05 90 bottom
R32  20K  [R0201]  46.79 20.05 315 bottom
R33  10K  [R0201]  80.57 57.51 270 top
R34  4.02K  [R0201]  3.61 39.1 0 top
R35  4.02K  [R0201]  3.61 38.34 180 top
R36  20K  [R0402]  3.74 28.3 180 bottom
R37  10K  [R0402]  43.74 26.52 180 bottom
R38  10K  [R0201]  3.61 44.69 0 top
R39  10K  [R0201]  2.21 43.67 0 top
R40  10K  [R0201]  3.61 43.67 0 top
R41  10K  [R0201]  16.05 43.03 0 bottom
R42  4.99K  [R0402]  16.31 45.07 0 top
R43  10K  [R0201]  30.66 8.74 90 top
R44  4.99K  [R0402]  17.07 48.5 0 bottom
R45  4.99K  [R0402]  17.07 53.19 0 bottom
R46  10K  [R0201]  62.79 3.79 180 bottom
R47  4.99K  [R0402]  59.23 15.6 270 bottom
R48  4.99K  [R0402]  60.63 17.13 270 bottom
R49  4.99K  [R0201]  22.79 10.78 90 top
R50  4.99K  [R0402]  16.44 13.44 90 bottom
R51  4.7K  [R0402]  2.97 42.78 0 bottom
R52  4.7K  [R0402]  2.97 41.38 0 bottom
R53  1K  [R0201]  39.93 35.03 270 bottom
R54  301  [R0402]  75.87 50.65 0 bottom
R55  1K  [R0402]  75.87 51.67 0 bottom
R56  10K  [R0201]  29.14 55.73 0 top
R57  4.7K  [R0402]  2.47 18.52 90 bottom
R58  4.7K  [R0402]  4.88 19.29 180 bottom
R59  1K  [R0402]  59.69 34.14 90 bottom
R60  0  [R0402]  45.32 14.94 270 bottom
R61  4.02K  [R0201]  75.24 40.75 0 bottom
R62  4.02K  [R0201]  75.24 41.51 180 bottom
R63  10K  [R0201]  76.51 48.24 180 bottom
R64  10K  [R0201]  76.51 49 0 bottom
R65  10K  [R0201]  74.86 48.24 0 bottom
R66  10K  [R0201]  74.86 49 180 bottom
R67  4.02K  [R0201]  77.78 40.75 180 bottom
R68  4.02K  [R0201]  77.78 41.51 0 bottom
R69  4.02K  [R0201]  10.47 38.59 180 top
R70  10K  [R0201]  11.74 38.21 180 top
R71  4.02K  [R0201]  14.53 38.21 0 top
R72  10K  [R0201]  14.53 38.97 180 top
R73  4.02K  [R0201]  14.4 39.73 180 top
R74  10K  [R0201]  14.4 40.49 0 top
R75  1K  [R0201]  93.78 31.99 0 bottom
R76  10K  [R0201]  46.79 4.55 0 bottom
R77  10K  [R0201]  47.93 4.05 270 bottom
R78  53.6K  [R0402]  26.72 6.33 270 top
R79  13.3K  [R0201]  26.49 9.51 270 top
R80  1  [R0402]  14.66 1.12 0 top
R81  10K  [R0402]  64.44 6.84 0 top
R101  49.9  [R0201]  71.3 40.11 180 top
R102  49.9  [R0201]  83.75 18.59 90 top
R109  4.99K  [R0402]  4.62 10.9 0 bottom
R111  10K  [R0201]  66.47 31.6 0 bottom
R113  130  [R0402]  31.68 54.97 0 top
R114  39  [R0603]  46.03 10.4 90 top
R116  20K  [R0402]  60 58.53 180 bottom
R119  20K  [R0402]  72.06 51.54 0 top
R120  20K  [R0402]  64.06 58.53 180 bottom
R121  20K  [R0402]  70.66 58.53 180 bottom
R122  20K  [R0402]  62.92 57.51 180 bottom
R123  1  [R0201]  61.9 25.13 0 bottom
R124  1  [R0201]  68.89 29.7 180 bottom
R125  14.3K  [R0201]  67.36 34.14 90 bottom
R133  1K  [R0201]  52.17 45.52 0 top
R134  240  [R0402]  18.21 17 180 bottom
R135  240  [R0402]  18.21 27.41 180 bottom
R136  120  [R0201]  52.12 43.42 0 top
R137  120  [R0201]  53.01 47.1 90 top
R138  120  [R0201]  52.12 44.18 0 top
R139  120  [R0201]  48.69 44.69 90 top
R140  120  [R0201]  56.82 47.1 90 top
R141  120  [R0201]  49.2 46.08 90 top
R142  80.6  [R0402]  57.2 40.49 90 top
R143  120  [R0201]  55.3 47.1 90 top
R144  120  [R0201]  50.22 47.1 90 top
R145  120  [R0201]  56.06 47.1 90 top
R146  120  [R0201]  50.98 47.1 90 top
R147  120  [R0201]  54.56 40.16 180 top
R148  120  [R0201]  53.77 47.1 90 top
R149  120  [R0201]  54.36 41.49 270 top
R150  120  [R0201]  51.74 47.1 90 top
R151  120  [R0201]  54.54 47.1 90 top
R152  120  [R0201]  49.71 42.02 180 top
R153  120  [R0201]  54.36 42.83 270 top
R154  120  [R0201]  52.12 42.65 0 top
R155  120  [R0201]  52.12 41.84 0 top
R156  120  [R0201]  52.12 40.14 0 top
R159  120  [R0201]  52.12 41.05 0 top
R160  120  [R0201]  59.74 41.76 90 bottom
R161  0  [R0402]  49.71 58.91 270 bottom
R162  120  [R0201]  49.79 39.4 180 top
R163  120  [R0201]  49.07 40.49 270 top
R165  240  [R0402]  56.44 22.71 0 top
R166  240  [R0402]  60.5 45.83 0 bottom
R167  4.7K  [R0402]  34.09 47.99 270 top
R168  4.7K  [R0402]  35.61 47.99 270 top
R169  4.7K  [R0402]  29.26 36.05 90 bottom
R172  130  [R0402]  39.3 48.75 180 top
R175  39  [R0603]  22.4 53.07 90 bottom
R176  8.06K  [R0402]  18.47 49.89 270 top
R178  10K  [R0402]  13.26 55.1 0 bottom
R191  1K  [R0402]  44.5 14.46 270 top
R194  1K  [R0402]  42.98 14.46 90 top
R221  10K  [R0402]  44.38 59.67 270 bottom
R222  10K  [R0402]  43.36 59.67 270 bottom
R302  35.7K  [R0201]  23.55 10.78 270 top
R303  21K  [R0201]  24.31 10.78 270 top
R306  10K  [R0201]  73.59 7.35 0 top
RX1A  U.FL-R-SMT-1(01)  [CNHIROSE-U_FL-R-SMT-1]  96.45 39.86 270 top
RX1B  U.FL-R-SMT-1(01)  [CNHIROSE-U_FL-R-SMT-1]  91.37 35.41 270 top
RX2A  U.FL-R-SMT-1(01)  [CNHIROSE-U_FL-R-SMT-1]  91.37 22.71 270 top
RX2B  U.FL-R-SMT-1(01)  [CNHIROSE-U_FL-R-SMT-1]  96.45 27.16 270 top
S1  CAS-120TB  [SWSML213W98H98]  3.74 9.76 0 top
S3  CAS-120TB  [SWSML213W98H98]  52.88 54.46 0 top
S4  CAS-120TB  [SWSML213W98H98]  46.79 54.46 0 top
SW1  7914J-1-000E  [SWSMSQ197H165]  38.03 4.43 180 top
T1  TCM1-63AX+  [TSML150W160H160]  77.27 40.88 270 top
T2  TCM1-63AX+  [TSML150W160H160]  77.52 34.78 0 top
T3  TCM1-63AX+  [TSML150W160H160]  77.65 21.32 180 top
T4  TCM1-63AX+  [TSML150W160H160]  77.27 27.29 270 top
T5  TCM1-63AX+  [TSML150W160H160]  67.62 39.73 0 top
T6  TCM1-63AX+  [TSML150W160H160]  62.03 39.99 90 top
T7  TCM1-63AX+  [TSML150W160H160]  70.66 20.3 270 top
T8  TCM1-63AX+  [TSML150W160H160]  62.92 20.43 180 top
TP2  TESTPAD  [TPSMC30]  55.17 5.44 0 top
TX1A  U.FL-R-SMT-1(01)  [CNHIROSE-U_FL-R-SMT-1]  96.45 48.75 270 top
TX1B  U.FL-R-SMT-1(01)  [CNHIROSE-U_FL-R-SMT-1]  91.37 53.19 270 top
TX2A  U.FL-R-SMT-1(01)  [CNHIROSE-U_FL-R-SMT-1]  91.37 13.82 270 top
TX2B  U.FL-R-SMT-1(01)  [CNHIROSE-U_FL-R-SMT-1]  96.45 9.38 270 top
TXM1  U.FL-R-SMT-1(01)  [CNHIROSE-U_FL-R-SMT-1]  91.37 44.3 270 top
TXM2  U.FL-R-SMT-1(01)  [CNHIROSE-U_FL-R-SMT-1]  96.45 18.27 270 top
U1  XC7Z035-L2FBG676I  [FBGA676]  34.22 30.59 180 top
U2  MT41K256M16TW-107:P  [FBGA96_C]  53.39 22.71 90 bottom
U3  MT41K256M16TW-107:P  [FBGA96_C]  53.39 39.48 90 bottom
U4  ADP5135  [QFN24_4X4_PAD2_6X2_6]  60 8.87 90 top
U5  ADG772BCPZ  [QFN10_1_6X1_3]  78.28 57.51 0 top
U6  ADP7102ACPZ-2.5  [QFN8_3X3_PAD2_44X1_7]  79.3 57.89 270 bottom
U7  ADM1166ACPZ  [QFN40_6X6_PAD4_6X4_6]  9.83 42.78 0 top
U8  ADM7160AUJZ-1.8  [TSOT-5]  78.16 54.08 90 bottom
U9  ADP7104ACPZ-3.3-R7  [QFN8_3X3_PAD2_44X1_7]  39.04 53.19 270 top
U10  88E1512-56QFN  [QFN56_8X8_PAD4_37X4_37]  21.64 7.09 180 bottom
U11  TXS02612RTWR  [QFN24_4X4_PAD2_5X2_5]  7.8 14.59 90 top
U13  N25Q256A11E1240  [TBGA24]  67.62 56.62 180 top
U14  TPS51206DSQR  [SON10_2X2_PAD1_5X0_9]  46.92 59.42 270 bottom
U15  USB3320C-EZK  [QFN32_5X5_PAD3_3X3_3]  22.91 52.94 90 top
U16  CDSOT23-SR208  [SOT23_6-2]  15.55 53.07 180 top
U17  AD9361BBCZ  [BGA144]  65.2 29.69 90 top
U18  ADP2386ACPZN  [QFN24_4X4_2PAD]  22.91 6.46 180 top
U19  ADP1754ACPZ-1.3  [QFN16_4X4_PAD2_1X2_1]  68.89 8.74 0 top
U20  ADP1754ACPZ-1.3  [QFN16_4X4_PAD2_1X2_1]  78.54 8.74 0 top
U21  TCA9517DGKR  [MSOP8]  3.99 23.35 180 bottom
U22  FXL4T245BQX  [DQFN14_3X2_5_PAD1_65X1_15]  56.69 31.48 90 top
U23  ADP7118AUJZ-3.3  [TSOT-5]  57.84 53.07 0 top
U24  AD7291BCPZ  [QFN20_4X4_PAD2_6X2_6]  76.13 44.94 180 bottom
Y1  33.333MEGHZ  [YSML98W79H35]  46.86 6.31 90 top
Y2  25MEGHZ  [YSML126W98H39]  33.33 12.81 0 top
Y3  24MEGHZ  [YSML98W79H35]  17.71 57.13 270 top
Y4  40MEGHz  [YSML126W98H47]  76.63 53.19 90 top

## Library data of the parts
C1 = CAP: alternate symbols: (); part number: CAP_SM-0.01UF,10V,10,E007201,C0201; tolerance: 10; signal model: DEFAULT_CAPACITOR_100000pF_1_2
C2 C3 C12 = CAP: alternate symbols: (); part number: CAP_SM-1UF,6.3V,10,E007449,C0402; tolerance: 10; signal model: DEFAULT_CAPACITOR_100000pF_1_2
C4 C43 C76 C77 C84 C102 C103 C122 C123 C311 C321 C322 C325 C326 C329 C330 C333 C334 C337 C340 C355 C356 C359 C360 = CAP: alternate symbols: (); part number: CAP_SM-0.01UF,10V,10,E007201,C0201; tolerance: 10
C5 C260 = CAP: Tolerance: 10; User Part Number: UPN; alternate symbols: (); part number: CAP_SM-4.7UF,16V,10,E020112,C0603; tolerance: 10
C6 C7 C104 = CAP: alternate symbols: (); part number: CAP_SM-0.001UF,25V,10,E006762,C0201; tolerance: 10
C8-C11 C25 = CAP: alternate symbols: (); part number: CAP_SM-18PF,50V,5,E017960,C0201; tolerance: 5; signal model: DEFAULT_CAPACITOR_100000pF_1_2
C13 C14 C16 C19 C20 = CAP: alternate symbols: (); part number: CAP_SM-0.001UF,25V,10,E006762,C0201; tolerance: 10; signal model: DEFAULT_CAPACITOR_100000pF_1_2
C15 C17 = CAP: alternate symbols: (); part number: CAP_SM-4.7UF,6.3V,10,E020089,C0402; tolerance: 10; signal model: DEFAULT_CAPACITOR_100000pF_1_2
C18 = CAP: alternate symbols: (); part number: CAP_SM-0.47UF,10V,10,E007611,C0402; tolerance: 10; signal model: DEFAULT_CAPACITOR_100000pF_1_2
C21-C24 = CAP: Tolerance: 20; User Part Number: UPN; alternate symbols: (); part number: CAP_SM-10UF,6.3V,20,E007143,C0603; tolerance: 20; signal model: DEFAULT_CAPACITOR_100000pF_1_2
C26 C29 C30 C32-C35 C51-C53 C56 = CAP: alternate symbols: (); part number: CAP_SM-18PF,50V,5,E017960,C0201; tolerance: 5
C27 C72 C88-C90 C107 C108 C114 C125 C143 C145 C146 C153 C162 C163 C170 C171 C178 C179 C189 C222 C228 = CAP: alternate symbols: (); part number: CAP_SM-0.47UF,10V,10,E007611,C0402; tolerance: 10
C28 C31 C37 C39 C42 C54 C55 C57 C73 C75 C93 C98 C119 C126-C132 C135-C137 C147-C152 C154-C157 C160 C164 C166 C168 C185-C187 C190 C201 C203 C206 C208 C211 C212 C217 C224-C227 C229-C242 C249 C250 = CAP: alternate symbols: (); part number: CAP_SM-0.1UF,16V,10,E007200,C0402; tolerance: 10
C36 C58 C78 C181-C183 C199 C219 = CAP: Tolerance: 10; User Part Number: UPN; alternate symbols: (); part number: CAP_SM-1UF,16V,10,E006882,C0603; tolerance: 10
C38 C61 C62 C65 C124 C134 C158 C191-C198 C200 C202 C204 C205 C210 C301 C312 C313 C362 C363 C365 = CAP: Tolerance: 20; User Part Number: UPN; alternate symbols: (); part number: CAP_SM-10UF,6.3V,20,E007143,C0603; tolerance: 20
C40 C41 C214 = CAP: alternate symbols: (); part number: CAP_SM-0.1UF,16V,10,E007200,C0402; tolerance: 10; signal model: DEFAULT_CAPACITOR_100000pF_1_2
C44 C85 = CAPP: Tolerance: 20; User Part Number: UPN; alternate symbols: (); part number: CAPP_SM-680UF,2.5V,20,E022765,CPLSML287W169H118; tolerance: 20
C45-C48 C66 C113 C188 C243-C246 C253 C310 C314 C315 C318 C319 C343 C344 C347 C348 C364 = CAP: alternate symbols: (); part number: CAP_SM-0.1UF,6.3V,10,E011567,C0201; tolerance: 10
C49 C50 C63 C64 C70 C71 C74 C86 C87 C99 C101 C106 C110 C111 C120 C121 C133 C140-C142 C144 C159 C161 C167 C169 C174-C177 C218 C220 C221 C223 = CAP: alternate symbols: (); part number: CAP_SM-4.7UF,6.3V,10,E020089,C0402; tolerance: 10
C59 C60 = CAP: Tolerance: 5; User Part Number: UPN; alternate symbols: (); part number: CAP_SM-27PF,50V,5,E000395,C0603; tolerance: 5
C67-C69 = CAP: Tolerance: 20; User Part Number: UPN; alternate symbols: (); part number: CAP_SM-22UF,6.3V,20,E021512,C0603; tolerance: 20
C79 C82 C83 = CAP: Tolerance: 20; User Part Number: UPN; alternate symbols: (); part number: CAP_SM-10UF,25V,20,E015584,C0805H60; tolerance: 20
C80 = CAP: alternate symbols: (); part number: CAP_SM-0.015UF,50V,10,E020595,C0402; tolerance: 10
C81 = CAP: Tolerance: 10; User Part Number: UPN; alternate symbols: (); part number: CAP_SM-0.22UF,16V,10,E000443,C0805; tolerance: 10
C91 C92 C94-C97 C109 C112 C115-C118 = CAP: alternate symbols: (); part number: CAP_SM-0.1UF,16V,20,E017331,C0201; tolerance: 20
C100 C138 C139 C172 C173 C180 C258 C259 C308 C309 = CAP: Tolerance: 20; User Part Number: UPN; alternate symbols: (); part number: CAP_SM-100UF,6.3V,20,E016591,C1206H71; tolerance: 20
C105 C320 C323 C324 C327 C328 C331 C332 C335 C336 C354 C357 C358 C361 = CAP: alternate symbols: (); part number: CAP_SM-1UF,6.3V,10,E007449,C0402; tolerance: 10
C165 C216 = CAP: alternate symbols: (); part number: CAP_SM-18PF,50V,5,E007476,C0402; tolerance: 5
C184 = CAP: Tolerance: 10; User Part Number: UPN; alternate symbols: (); part number: CAP_SM-1UF,16V,10,E006882,C0603; tolerance: 10; signal model: DEFAULT_CAPACITOR_100000pF_1_2
C207 C209 C213 C215 = CAP: alternate symbols: (); part number: CAP_SM-220PF,50V,5,E012615,C0402; tolerance: 5
C247 = CAP: Tolerance: 10; User Part Number: UPN; alternate symbols: (); part number: CAP_SM-2.2UF,16V,10,E020871,C0603; tolerance: 10
C248 C305 = CAP: Tolerance: 10; User Part Number: UPN; alternate symbols: (); part number: CAP_SM-2.2UF,6.3V,10,E006877,C0603; tolerance: 10
C251 = CAP: Tolerance: 20; User Part Number: UPN; alternate symbols: (); part number: CAP_SM-47UF,6.3V,20,E008247,C0805H60; tolerance: 20
C252 = CAP: Tolerance: 10; User Part Number: UPN; alternate symbols: (); part number: CAP_SM-0.039UF,16V,10,E012650,C0603; tolerance: 10
C254 = CAP: alternate symbols: (); part number: CAP_SM-1UF,16V,20,E020695,C0402; tolerance: 20
C255 = CAP: alternate symbols: (); part number: CAP_SM-0.0022UF,10V,10,E021478,C0201; tolerance: 10
C256 = CAP: alternate symbols: (); part number: CAP_SM-39PF,25V,5,E026816,C0201; tolerance: 5
C257 = CAP: Tolerance: 10; User Part Number: UPN; alternate symbols: (); part number: CAP_SM-2.2UF,6.3V,10,E005843,C0603; tolerance: 10
C341 C342 = CAP: alternate symbols: (); part number: CAP_SM-10UF,6.3V,20,E020966,C0402; tolerance: 20
D1 = DIOSCHOTTKY3P_V10: User Part Number: UPN; Tolerance: N/A; alternate symbols: (); part number: DIOSCHOTTKY3P_V10_SM-BAT54C,30V,N/A,E021001,SOT23; tolerance: N/A
D3 D4 DS1 = DIOLED: Tolerance: N/A; User Part Number: UPN; alternate symbols: (); part number: DIOLED_SM-LG L29K-G2J1-24-Z,N/A,N/A,E010948,LED0603-2; tolerance: N/A
E1 E12 = FERRITE: Tolerance: 25; User Part Number: UPN; alternate symbols: (); part number: FERRITE_SM-220OHM,25,E017491,L0805; tolerance: 25
E2-E4 E7-E9 E11 E14-E16 = FERRITE: Tolerance: 25; User Part Number: UPN; alternate symbols: (); part number: FERRITE_SM-100OHM,25,E012241,L0805; tolerance: 25
E10 = FERRITE: Tolerance: 25; User Part Number: UPN; alternate symbols: (); part number: FERRITE_SM-75OHM,25,E017348,L0402; tolerance: 25
J3 = CN9P_4GND: User Part Number: UPN; Tolerance: N/A; alternate symbols: (); part number: CN9P_4GND_SM-DM3CS-SF,E022379,CNHIROSEDM3CS-SF; tolerance: N/A
JP1-JP4 = NC3P_JMPR: Tolerance: N/A; User Part Number: UPN; alternate symbols: (); part number: NC3P_JMPR_SM-3PIN_SOLDER_JUMPER,E005606,JPRSLD03; tolerance: N/A
JX1-JX4 = CN100P_ODD_EVEN: User Part Number: UPN; Tolerance: N/A; alternate symbols: (); part number: CN100P_ODD_EVEN_SM-61082-101400LF,E022296,CNFCI61082-101400; tolerance: N/A
L1-L4 L8-L11 = IND: Tolerance: 5; User Part Number: UPN; alternate symbols: (); part number: IND_SM-330NH,5,E006599,L0805-F; tolerance: 5
L5-L7 = IND: Tolerance: 20; User Part Number: UPN; alternate symbols: (); part number: IND_SM-1UH,20,E015810,LSMSQ118H47; tolerance: 20
L12 = FERRITE: Tolerance: 25; User Part Number: UPN; alternate symbols: (); part number: FERRITE_SM-600OHMS,25,E007179,L0603; tolerance: 25
L13 = IND: User Part Number: UPN; Tolerance: 20; alternate symbols: (); part number: IND_SM-330NH,20,E022164,LSMSQ157H63; tolerance: 20
L301 = IND: User Part Number: UPN; Tolerance: 20; alternate symbols: (); part number: IND_SM-700NH,20,E022166,LSMSQ157H63; tolerance: 20
M1 = MODLT15CCC2243A: Tolerance: N/A; User Part Number: UPN; alternate symbols: (); part number: MODLT15CCC2243A_SM-LT15CCC2243A,E023383,MLT15CCC2243A; tolerance: N/A
P1 = CN10P_AB: Tolerance: N/A; User Part Number: UPN; alternate symbols: (); part number: CN10P_AB_SM-5147733-4,E023428,CNTE5147733-4; tolerance: N/A
Q1-Q4 = TRANBSS138: User Part Number: UPN; Tolerance: N/A; alternate symbols: (); part number: TRANBSS138_SM-BSS138TA,E004635,SOT23; tolerance: N/A
Q5 Q6 Q14 = TRANNMOSFET_V8: User Part Number: UPN; Tolerance: N/A; alternate symbols: (); part number: TRANNMOSFET_V8_SM-BSS138LT1G,E018770,SOT23; tolerance: N/A
Q7 Q8 Q10 Q12 = TRANNMOSFET_V29: User Part Number: UPN; Tolerance: N/A; alternate symbols: (); part number: TRANNMOSFET_V29_SM-SI1050X-T1-GE3,E022478,SOT-563; tolerance: N/A
Q9 Q11 Q13 = TRANNMOSFET_V31: Tolerance: N/A; User Part Number: UPN; alternate symbols: (); part number: TRANNMOSFET_V31_SM-FDMA430NZ,E025877,MLP6_2X2_PAD_9X1_PAD_2X_56; tolerance: N/A
R1 R2 = RES: alternate symbols: (); part number: RES_SM-10,E013982,1/20W,1,R0201; tolerance: 1
R3 R36 R116 R119-R122 = RES: alternate symbols: (); part number: RES_SM-20K,E003791,1/16W,1,R0402; tolerance: 1
R4 = RES: alternate symbols: (); part number: RES_SM-4.99K,E006643,1/16W,1,R0402; tolerance: 1; signal model: DEFAULT_RESISTOR_0.001OHM_1_2
R5 R101 R102 = RES: alternate symbols: (); part number: RES_SM-49.9,E007693,1/20W,1,R0201; tolerance: 1
R6 R9 R12 R161 = RES: alternate symbols: (); part number: RES_SM-0,E010661,1/16W,1,R0402; tolerance: 1
R7 R21 R22 R26 R27 R29 R37 R81 R178 R221 R222 = RES: alternate symbols: (); part number: RES_SM-10K,E003751,1/16W,1,R0402; tolerance: 1
R8 = RES: alternate symbols: (); part number: RES_SM-10K,E003751,1/16W,1,R0402; tolerance: 1; signal model: DEFAULT_RESISTOR_0.001OHM_1_2
R10 = RES: alternate symbols: (); part number: RES_SM-100,E016329,1/10W,1,R0402; tolerance: 1
R11 R42 R44 R45 R47 R48 R50 R109 = RES: alternate symbols: (); part number: RES_SM-4.99K,E006643,1/16W,1,R0402; tolerance: 1
R13 R14 = RES: alternate symbols: (); part number: RES_SM-1K,E003763,1/10W,1,R0402; tolerance: 1; signal model: DEFAULT_RESISTOR_100.000000OHM_1_2
R15 R55 R59 R191 R194 = RES: alternate symbols: (); part number: RES_SM-1K,E003763,1/10W,1,R0402; tolerance: 1
R16 = RES: alternate symbols: (); part number: RES_SM-1K,E003763,1/10W,1,R0402; tolerance: 1; signal model: DEFAULT_RESISTOR_0.001OHM_1_2
R17 R18 = RES: alternate symbols: (); part number: RES_SM-220,E011432,1/16W,1,R0402; tolerance: 1
R19 R60 = RES: alternate symbols: (); part number: RES_SM-0,E003438,N/A,5,R0402; tolerance: 5
R20 R23 R30 R33 R38-R41 R43 R46 R56 R63-R66 R70 R72 R74 R76 R77 R111 R306 = RES: alternate symbols: (); part number: RES_SM-10K,E004011,1/20W,1,R0201; tolerance: 1
R24 = RES: Tolerance: 1; User Part Number: UPN; alternate symbols: (); part number: RES_SM-16.9K,E014233,1/10W,1,R0603; tolerance: 1
R25 = RES: Tolerance: 1; User Part Number: UPN; alternate symbols: (); part number: RES_SM-26.1K,E024699,1/10W,1,R0603; tolerance: 1
R28 R134 R135 R165 R166 = RES: alternate symbols: (); part number: RES_SM-240,E010877,1/16W,1,R0402; tolerance: 1
R31 R32 = RES: alternate symbols: (); part number: RES_SM-20K,E004013,1/20W,1,R0201; tolerance: 1
R34 R35 R61 R62 R67-R69 R71 R73 = RES: alternate symbols: (); part number: RES_SM-4.02K,E023201,1/20W,1,R0201; tolerance: 1
R49 = RES: alternate symbols: (); part number: RES_SM-4.99K,E027454,1/20W,1,R0201; tolerance: 1
R51 R52 R57 R58 R167-R169 = RES: alternate symbols: (); part number: RES_SM-4.7K,E008190,1/16W,1,R0402; tolerance: 1
R53 R75 R133 = RES: alternate symbols: (); part number: RES_SM-1K,E004010,1/20W,1,R0201; tolerance: 1
R54 = RES: alternate symbols: (); part number: RES_SM-301,E011195,1/16W,1,R0402; tolerance: 1
R78 = RES: alternate symbols: (); part number: RES_SM-53.6K,E023305,1/16W,1,R0402; tolerance: 1
R79 = RES: alternate symbols: (); part number: RES_SM-13.3K,E027455,1/20W,1,R0201; tolerance: 1
R80 = RES: alternate symbols: (); part number: RES_SM-1,E010031,1/16W,5,R0402; tolerance: 5
R113 R172 = RES: alternate symbols: (); part number: RES_SM-130,E003795,1/16W,1,R0402; tolerance: 1
R114 R175 = RES: Tolerance: 1; User Part Number: UPN; alternate symbols: (); part number: RES_SM-39,E004235,1/16W,1,R0603; tolerance: 1
R123 R124 = RES: alternate symbols: (); part number: RES_SM-1,E014056,1/20W,1,R0201
R125 = RES: alternate symbols: (); part number: RES_SM-14.3K,E014068,1/20W,1,R0201; tolerance: 1
R136-R141 R143-R156 R159 R160 R162 R163 = RES: alternate symbols: (); part number: RES_SM-120,E011549,1/20W,1,R0201; tolerance: 1
R142 = RES: alternate symbols: (); part number: RES_SM-80.6,E022369,1/16W,0.1,R0402; tolerance: 0.1
R176 = RES: alternate symbols: (); part number: RES_SM-8.06K,E021385,1/10W,1,R0402; tolerance: 1
R302 = RES: alternate symbols: (); part number: RES_SM-35.7K,E019520,1/20W,1,R0201; tolerance: 1
R303 = RES: alternate symbols: (); part number: RES_SM-21K,E027440,1/20W,1,R0201; tolerance: 1
RX1A RX1B RX2A RX2B TX1A TX1B TX2A TX2B TXM1 TXM2 = CNBNC3P: Tolerance: N/A; User Part Number: UPN; alternate symbols: (); part number: CNBNC3P_SM-U.FL-R-SMT-1(01),E022198,CNHIROSE-U_FL-R-SMT-1; tolerance: N/A
S1 S3 S4 = SWSPDT_V2: Tolerance: N/A; User Part Number: UPN; alternate symbols: (); part number: SWSPDT_V2_SM-CAS-120TB,E012554,SWSML213W98H98; tolerance: N/A
